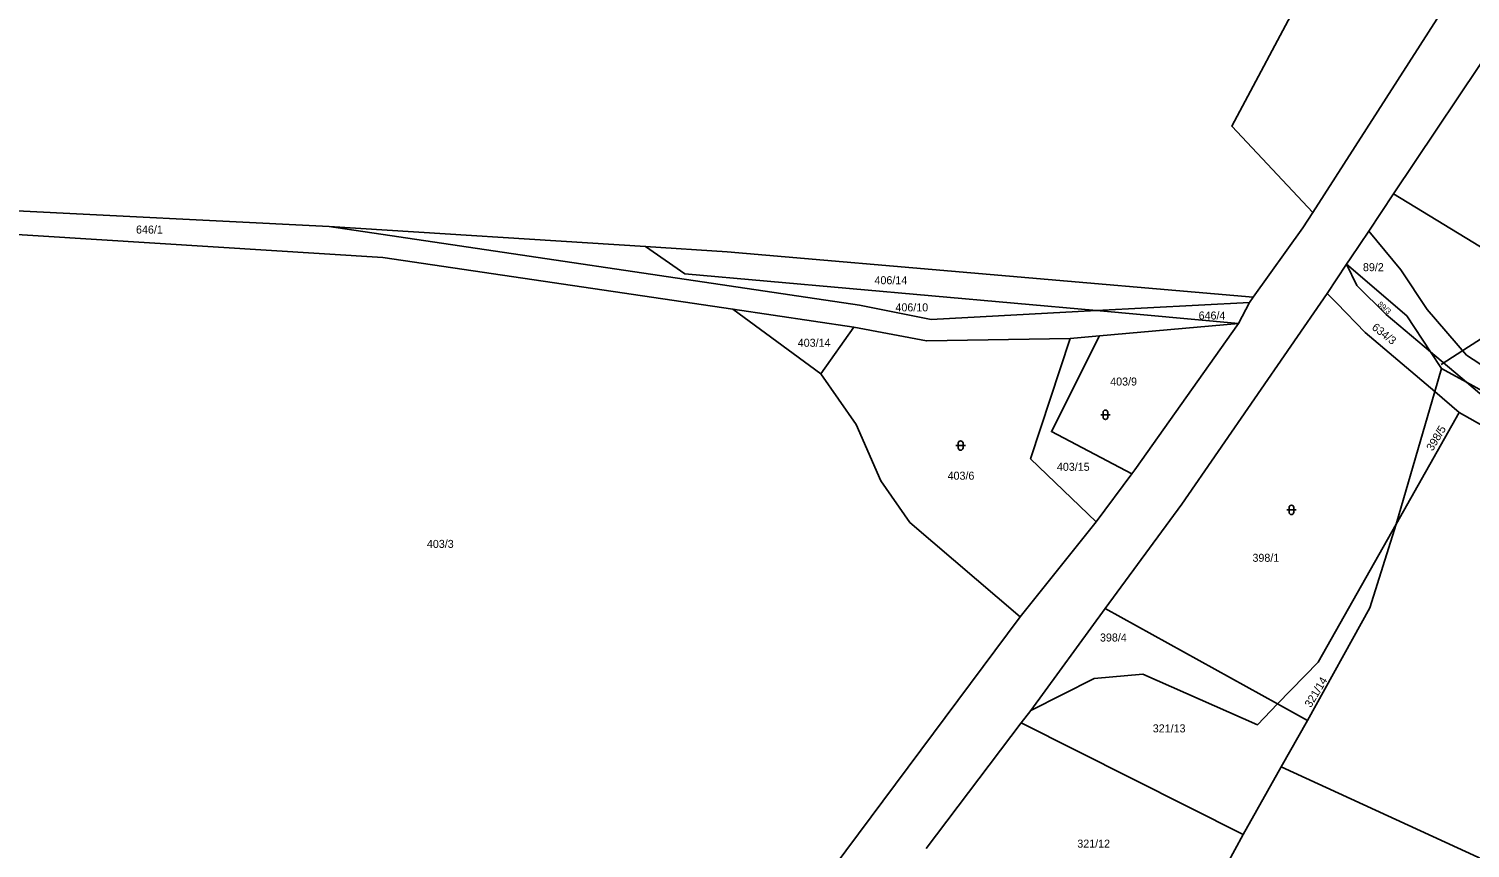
# Model space of a CAD drawing. Extents: x -744566 to -741843, y -1128407 to -1126744.
# Drawn here: x -743962 to -743655.8, y -1127447.3 to -1127273.4 of the extents above; entities that cross this region are included whole.
import ezdxf

# ---------------------------------------------------------------- set-up
doc = ezdxf.new("R2010")
doc.units = 0
for name, color, linetype in [('Hranice parcel', 7, 'Continuous'), ('Parcelní čísla', 7, 'Continuous'), ('Pop  PČ popisy', 7, 'Continuous'), ('Značky kultur', 7, 'Continuous')]:
    doc.layers.add(name, color=color, linetype=linetype)

msp = doc.modelspace()

# ---------------------------------------------------------------- linework, layer by layer
at = {"layer": 'Hranice parcel'}
for p, q in [((-743658.6, -1127264.57), (-743689.23, -1127312.32)), ((-743649.24, -1127274.28), (-743672.05, -1127308.38)), ((-743677.33, -1127316.28), (-743672.05, -1127308.38)), ((-743994.91, -1127310.47), (-743898.15, -1127315.31)), ((-743898.15, -1127315.31), (-743830.99, -1127319.56)), ((-743686.17, -1127329.52), (-743682.05, -1127323.29)), ((-743701.89, -1127330.35), (-743702.67, -1127331.44)), ((-743793.75, -1127346.62), (-743812.42, -1127332.86)), ((-743812.42, -1127332.86), (-743786.7, -1127336.65)), ((-743735.17, -1127333.17), (-743702.67, -1127331.44)), ((-743705.01, -1127335.87), (-743735.17, -1127333.17)), ((-743702.67, -1127331.44), (-743705.01, -1127335.87)), ((-743705.01, -1127335.87), (-743734.53, -1127338.5)), ((-743793.75, -1127346.62), (-743786.7, -1127336.65)), ((-743740.8, -1127339.06), (-743734.53, -1127338.5)), ((-743661.88, -1127345.44), (-743664.22, -1127341.91)), ((-743664.22, -1127341.91), (-743656.57, -1127348.37)), ((-743663.32, -1127350.36), (-743661.88, -1127345.44)), ((-743661.88, -1127345.44), (-743656.57, -1127348.37)), ((-743671.53, -1127378.48), (-743663.32, -1127350.36)), ((-743658.11, -1127354.78), (-743663.32, -1127350.36)), ((-743658.11, -1127354.78), (-743671.53, -1127378.48)), ((-743727.68, -1127367.83), (-743735.23, -1127377.99)), ((-743735.23, -1127377.99), (-743751.42, -1127398.16)), ((-743749.15, -1127418.02), (-743733.3, -1127396.4)), ((-743733.3, -1127396.4), (-743696.72, -1127416.64)), ((-743751.15, -1127420.66), (-743749.15, -1127418.02)), ((-743690.34, -1127420.17), (-743696.72, -1127416.64)), ((-743771.38, -1127447.34), (-743751.15, -1127420.66)), ((-743704.03, -1127444.35), (-743751.15, -1127420.66)), ((-743695.91, -1127430.01), (-743690.34, -1127420.17)), ((-743704.03, -1127444.35), (-743695.91, -1127430.01)), ((-743695.91, -1127430.01), (-743643.11, -1127454.25)), ((-743719.41, -1127472.79), (-743704.03, -1127444.35))]:
    msp.add_line(p, q, dxfattribs=at)
for points in [[(-743689.23, -1127312.32), (-743706.45, -1127294.03), (-743676.81, -1127238.46)], [(-743672.05, -1127308.38), (-743638.39, -1127328.87), (-743608.18, -1127342.94)], [(-743812.42, -1127332.86), (-743886.76, -1127321.92), (-743996.07, -1127315.02)], [(-743701.89, -1127330.35), (-743691.32, -1127315.58), (-743689.23, -1127312.32)], [(-743735.17, -1127333.17), (-743770.32, -1127335.04), (-743785.55, -1127332.01), (-743898.15, -1127315.31)], [(-743682.05, -1127323.29), (-743681.13, -1127321.96), (-743677.33, -1127316.28)], [(-743677.33, -1127316.28), (-743670.54, -1127324.52), (-743664.92, -1127332.9), (-743656.54, -1127342.61), (-743635.91, -1127356.08), (-743619.02, -1127370.74)], [(-743735.17, -1127333.17), (-743822.64, -1127325.34), (-743830.99, -1127319.56)], [(-743830.99, -1127319.56), (-743813.6, -1127320.66), (-743701.89, -1127330.35)], [(-743682.05, -1127323.29), (-743669.28, -1127334.27), (-743664.22, -1127341.91)], [(-743682.05, -1127323.29), (-743679.84, -1127327.83), (-743673.62, -1127333.98), (-743664.22, -1127341.91)], [(-743686.17, -1127329.52), (-743717.04, -1127374.23), (-743733.3, -1127396.4)], [(-743663.32, -1127350.36), (-743678.08, -1127337.84), (-743684.1, -1127331.61), (-743686.17, -1127329.52)], [(-743727.68, -1127367.83), (-743727.05, -1127366.98), (-743705.01, -1127335.87)], [(-743786.7, -1127336.65), (-743771.3, -1127339.6), (-743740.8, -1127339.06)], [(-743740.8, -1127339.06), (-743749.17, -1127364.64), (-743735.23, -1127377.99)], [(-743734.53, -1127338.5), (-743744.74, -1127358.84), (-743727.68, -1127367.83)], [(-743751.42, -1127398.16), (-743774.81, -1127378.12), (-743780.97, -1127369.29), (-743786.2, -1127357.34), (-743793.75, -1127346.62)], [(-743656.57, -1127348.37), (-743640.77, -1127357.07), (-743633.94, -1127362.12)], [(-743656.57, -1127348.37), (-743653.73, -1127350.76), (-743633.94, -1127362.12)], [(-743618.94, -1127377.12), (-743622.79, -1127374.68), (-743658.11, -1127354.78)], [(-743696.72, -1127416.64), (-743688.11, -1127407.75), (-743671.53, -1127378.48)], [(-743690.34, -1127420.17), (-743677.11, -1127396.22), (-743671.53, -1127378.48)], [(-743829.49, -1127502.59), (-743827.26, -1127499.85), (-743798.95, -1127461.99), (-743751.42, -1127398.16)], [(-743696.72, -1127416.64), (-743700.98, -1127421.05), (-743725.34, -1127410.33), (-743735.67, -1127411.25), (-743749.15, -1127418.02)]]:
    msp.add_lwpolyline(points, dxfattribs=at)
at = {"layer": 'Pop  PČ popisy'}
for p, q in [((-743656.14, -1127340.86), (-743653.623, -1127339.226)), ((-743661.92, -1127344.63), (-743656.14, -1127340.86))]:
    msp.add_line(p, q, dxfattribs=at)
at = {"layer": 'Značky kultur'}
for p, q in [((-743733.781, -1127354.781), (-743733.781, -1127355.782)), ((-743732.779, -1127355.782), (-743732.779, -1127354.781)), ((-743734.281, -1127355.281), (-743732.279, -1127355.281)), ((-743765.031, -1127361.811), (-743763.029, -1127361.811)), ((-743764.531, -1127361.311), (-743764.531, -1127362.312)), ((-743763.529, -1127362.312), (-743763.529, -1127361.311)), ((-743694.761, -1127375.461), (-743692.759, -1127375.461)), ((-743694.261, -1127374.961), (-743694.261, -1127375.962)), ((-743693.259, -1127375.962), (-743693.259, -1127374.961))]:
    msp.add_line(p, q, dxfattribs=at)
for centre, start, end in [((-743733.28, -1127354.781), 0, 180), ((-743733.28, -1127355.781), 180, 359.98789), ((-743764.03, -1127361.311), 0, 180), ((-743764.03, -1127362.311), 180, 359.98789), ((-743693.76, -1127374.961), 0, 180), ((-743693.76, -1127375.961), 180, 359.98789)]:
    msp.add_arc(centre, 0.5, start, end, dxfattribs=at)

# ---------------------------------------------------------------- texts
at = {"layer": 'Parcelní čísla'}
for s, p in [('646/1', (-743939.2, -1127316.82)), ('89/2', (-743678.57, -1127324.8)), ('406/14', (-743782.33, -1127327.57)), ('406/10', (-743777.88, -1127333.33)), ('646/4', (-743713.48, -1127335.06)), ('403/14', (-743798.63, -1127340.84)), ('403/9', (-743732.26, -1127349.07)), ('403/15', (-743743.58, -1127367.17)), ('403/6', (-743766.803, -1127369.06)), ('403/3', (-743877.41, -1127383.53)), ('398/1', (-743702.04, -1127386.48)), ('398/4', (-743734.43, -1127403.4)), ('321/13', (-743723.22, -1127422.69)), ('321/12', (-743739.25, -1127447.15))]:
    msp.add_text(s, height=1.7, dxfattribs=at).set_placement(p)
for s, height, rotation, p in [('89/3', 1.19, 319, (-743675.56, -1127331.989)), ('634/3', 1.7, 322, (-743676.823, -1127337.009)), ('398/5', 1.7, 59, (-743663.771, -1127363.097)), ('321/14', 1.7, 59, (-743689.631, -1127417.557))]:
    msp.add_text(s, height=height, rotation=rotation, dxfattribs=at).set_placement(p)

doc.saveas('drawing.dxf')
